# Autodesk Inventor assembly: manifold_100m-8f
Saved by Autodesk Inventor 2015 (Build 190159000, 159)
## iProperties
Created: 2021-02
Part Number: manifold_100m-8f
Checked By: TraceParts S.A.
Catalog Web Link: www.traceparts.com
Document SubType Name: Assembly
Designer: TraceParts
Company: TraceParts S.A.
Author: TraceParts
REFERENCE: 100M-8F
DESIGN: Manifold for 4V series solenoid valve 100M-8F
SUPPLIER: ZheJiang XingChen pneumatic Co., LTD
TraceParts.PartNumber: 50-16072015-087160
TraceParts.PartTitle: Manifold for 4V series solenoid valve
TraceParts.InstanceId: 50-16072015-0871609TEDEE2C3QYPV70EKVD1JWSSP
TraceParts.PartStatus: Published
TraceParts.PartVersion: 1.0.8
TRACEPARTS: TRACEPARTS
TraceParts.PartLanguage: en
TraceParts.ClassPath: XINGCHEN_PNEUMATIC:50-16072015-087160
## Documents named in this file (3)
- C:\TPO v2\SharedFS\Outgoing\manifold_100m-8f.iam
- C:\TPO v2\SharedFS\Outgoing\manifold_100m-8f_01.ipt
- C:\TPO v2\SharedFS\Outgoing\manifold_100m-8f_02.ipt
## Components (2 placed, 2 different names)
1. manifold_100m-8f_01:1
2. manifold_100m-8f_02:1
